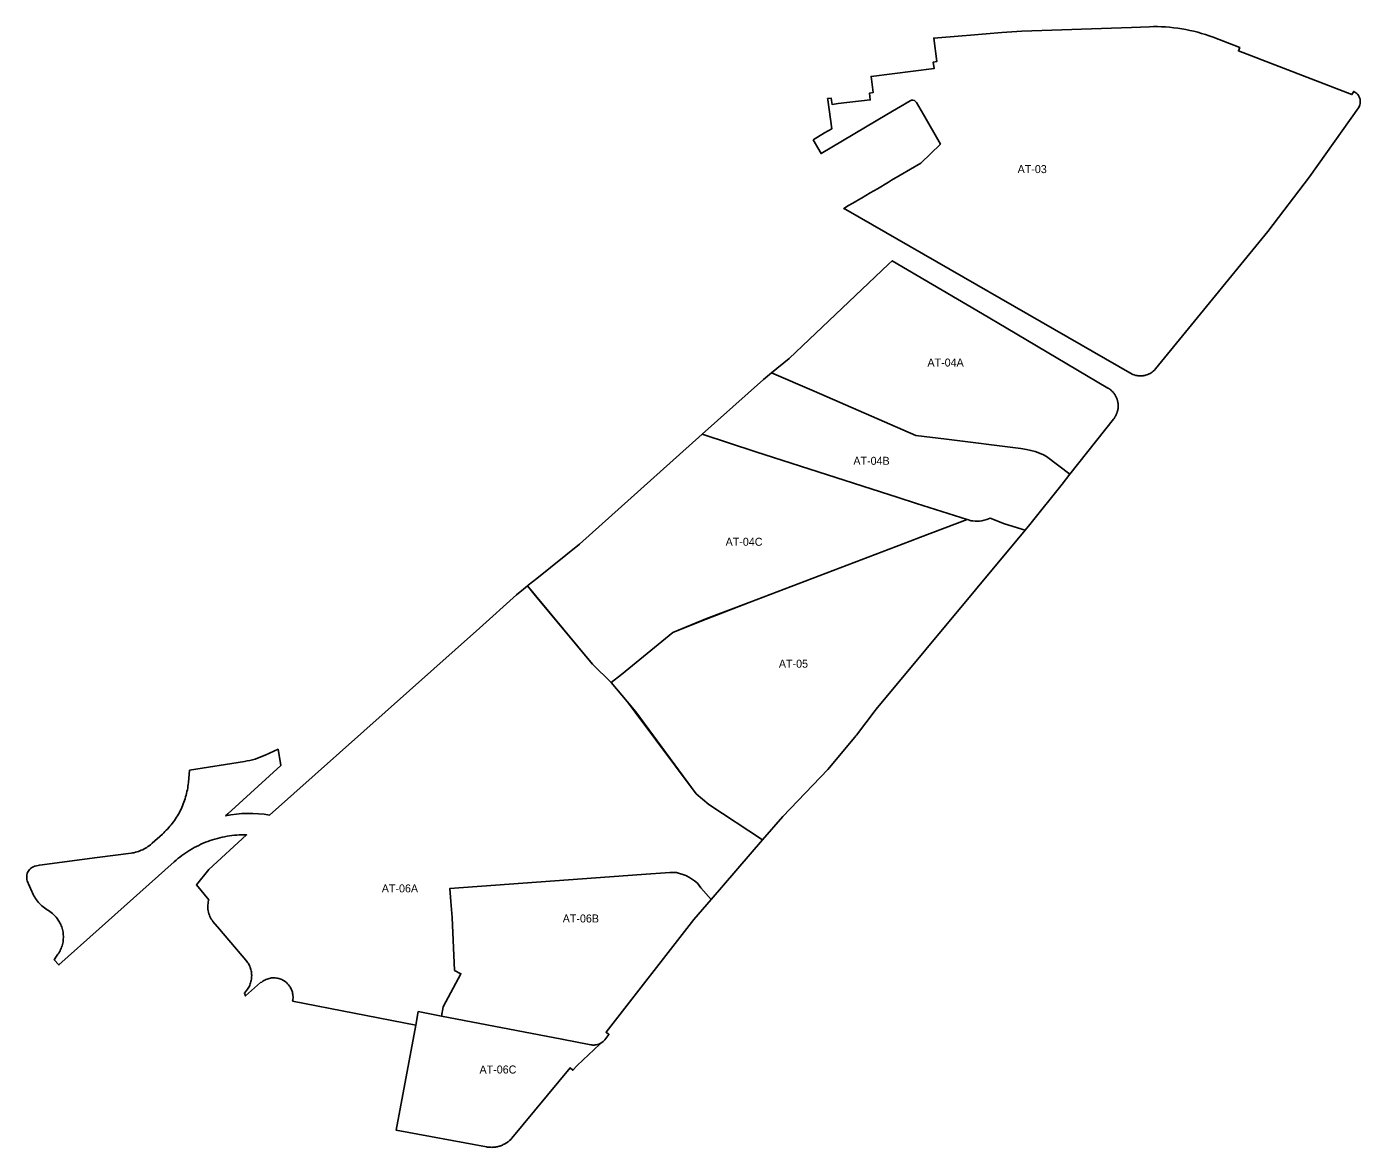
# Model space of a CAD drawing. Extents: x 428342 to 437063, y 4455780 to 4463043.
# Drawn here: x 431310 to 432143, y 4458647 to 4459347 of the extents above; entities that cross this region are included whole.
import ezdxf

# ---------------------------------------------------------------- set-up
doc = ezdxf.new("R2010")
doc.units = 0
doc.layers.add('AMB_SUNC-Residenciales', color=7, linetype='Continuous')
doc.layers.add('AMB_SUNC-Txt', color=7, linetype='Continuous')

msp = doc.modelspace()

# ---------------------------------------------------------------- linework, layer by layer
at = {"layer": 'AMB_SUNC-Residenciales'}
for points in [[(431800.91, 4459276.49), (431805.96, 4459267.89), (431847.1, 4459292.35), (431861.59, 4459300.94), (431862.46, 4459301.19), (431863.36, 4459301.2), (431864.24, 4459300.98), (431865.03, 4459300.53), (431865.67, 4459299.9), (431869.95, 4459292.35), (431880.49, 4459273.81), (431868.21, 4459261.94), (431855.36, 4459254.35), (431850, 4459251.19), (431847.99, 4459250), (431841.15, 4459245.96), (431836.62, 4459243.29), (431831.13, 4459240.05), (431828.81, 4459238.69), (431828.23, 4459238.36), (431827.15, 4459237.72), (431825.34, 4459236.66), (431823.11, 4459235.36), (431820.13, 4459233.62), (431821.47, 4459232.89), (432000.41, 4459130.05), (432000.83, 4459129.86), (432001.49, 4459129.6), (432002.64, 4459129.25), (432003.37, 4459129.09), (432004.11, 4459128.98), (432004.61, 4459128.93), (432005.11, 4459128.9), (432005.62, 4459128.89), (432006.13, 4459128.91), (432006.65, 4459128.94), (432007.16, 4459129), (432007.67, 4459129.08), (432008.17, 4459129.19), (432008.68, 4459129.31), (432009.42, 4459129.54), (432010.14, 4459129.81), (432010.84, 4459130.12), (432011.51, 4459130.48), (432012.15, 4459130.88), (432012.76, 4459131.31), (432013.52, 4459131.93), (432014.21, 4459132.59), (432014.83, 4459133.29), (432026.2, 4459147.18), (432085.16, 4459219.17), (432111.09, 4459253.37), (432141.7, 4459296.46), (432142.11, 4459297.15), (432142.35, 4459297.68), (432142.61, 4459298.44), (432142.79, 4459299.23), (432142.86, 4459299.83), (432142.88, 4459300.43), (432142.83, 4459301.23), (432142.68, 4459302), (432142.46, 4459302.74), (432142.15, 4459303.47), (432141.75, 4459304.16), (432141.28, 4459304.81), (432140.72, 4459305.4), (432140.11, 4459305.93), (432139.45, 4459306.37), (432138.75, 4459306.74), (432137.59, 4459304.78), (432066.72, 4459332.06), (432067.53, 4459334.16), (432050.87, 4459340.57), (432048.5, 4459341.45), (432046.11, 4459342.27), (432043.69, 4459343.03), (432041.25, 4459343.72), (432038.79, 4459344.36), (432036.31, 4459344.94), (432033.81, 4459345.45), (432031.3, 4459345.9), (432028.79, 4459346.28), (432026.26, 4459346.6), (432023.73, 4459346.86), (432021.19, 4459347.05), (432018.66, 4459347.18), (432016.12, 4459347.24), (432013.59, 4459347.24), (432011.07, 4459347.17), (432000, 4459346.74), (431931.28, 4459344.4), (431918.97, 4459343.68), (431899.26, 4459341.99), (431894.1, 4459341.56), (431876.38, 4459340.07), (431878.23, 4459325.45), (431876.03, 4459325.13), (431876.54, 4459321.05), (431837.23, 4459316.16), (431838.47, 4459306.06), (431836.21, 4459305.67), (431836.69, 4459301.49), (431816.67, 4459299.11), (431812.82, 4459298.65), (431812.48, 4459301.03), (431812.27, 4459302.51), (431810.05, 4459302.25), (431810.14, 4459301.58), (431812.6, 4459283.41), (431808.18, 4459280.83), (431800.91, 4459276.49)], [(431774.96, 4459130.86), (431801.66, 4459119.37), (431865.17, 4459091.68), (431884.21, 4459089.31), (431930.82, 4459083.49), (431934.21, 4459082.9), (431937.01, 4459082.28), (431939.76, 4459081.57), (431942.41, 4459080.64), (431944.83, 4459079.56), (431946.88, 4459078.53), (431961.4, 4459067.38), (431988.58, 4459101.84), (431988.79, 4459102.1), (431989, 4459102.38), (431989.2, 4459102.66), (431989.4, 4459102.94), (431989.59, 4459103.24), (431989.77, 4459103.53), (431989.94, 4459103.84), (431990.11, 4459104.15), (431990.27, 4459104.46), (431990.42, 4459104.79), (431990.56, 4459105.11), (431990.69, 4459105.44), (431990.82, 4459105.77), (431990.93, 4459106.11), (431991.04, 4459106.45), (431991.14, 4459106.8), (431991.22, 4459107.14), (431991.3, 4459107.49), (431991.37, 4459107.84), (431991.43, 4459108.19), (431991.48, 4459108.54), (431991.51, 4459108.9), (431991.54, 4459109.25), (431991.56, 4459109.6), (431991.57, 4459109.95), (431991.57, 4459110.31), (431991.56, 4459110.65), (431991.55, 4459111), (431991.52, 4459111.35), (431991.48, 4459111.69), (431991.44, 4459112.03), (431991.38, 4459112.37), (431991.32, 4459112.7), (431991.25, 4459113.04), (431991.17, 4459113.38), (431991.07, 4459113.71), (431990.97, 4459114.04), (431990.86, 4459114.38), (431990.75, 4459114.71), (431990.62, 4459115.03), (431990.48, 4459115.36), (431990.33, 4459115.68), (431990.18, 4459116), (431990.01, 4459116.32), (431989.84, 4459116.63), (431989.66, 4459116.93), (431989.47, 4459117.24), (431989.27, 4459117.53), (431989.06, 4459117.82), (431988.85, 4459118.11), (431988.62, 4459118.39), (431988.39, 4459118.66), (431988.16, 4459118.92), (431987.91, 4459119.18), (431987.66, 4459119.43), (431987.41, 4459119.68), (431987.15, 4459119.91), (431986.88, 4459120.14), (431986.61, 4459120.36), (431986.33, 4459120.57), (431986.05, 4459120.78), (431985.77, 4459120.97), (431985.48, 4459121.16), (431985.19, 4459121.33), (431921.63, 4459158.88), (431906.78, 4459167.65), (431850.39, 4459200.95), (431848.01, 4459198.69), (431785.93, 4459139.85), (431774.96, 4459130.86)], [(431731.67, 4459092.45), (431765.19, 4459081.52), (431854.21, 4459052.89), (431865.64, 4459049.22), (431897.3, 4459039.04), (431897.98, 4459038.84), (431899.01, 4459038.57), (431899.81, 4459038.41), (431900.81, 4459038.26), (431902.28, 4459038.12), (431903.79, 4459038.1), (431904.92, 4459038.16), (431906.44, 4459038.34), (431907.95, 4459038.64), (431909.61, 4459039.11), (431911.57, 4459039.89), (431920.64, 4459036.52), (431933.41, 4459032.4), (431936.45, 4459036.05), (431937.29, 4459037.06), (431956.59, 4459061.29), (431961.4, 4459067.38), (431946.88, 4459078.53), (431944.83, 4459079.56), (431942.41, 4459080.64), (431939.76, 4459081.57), (431937.01, 4459082.28), (431934.21, 4459082.9), (431930.82, 4459083.49), (431884.21, 4459089.31), (431865.17, 4459091.68), (431801.66, 4459119.37), (431774.96, 4459130.86), (431769.96, 4459126.75), (431731.67, 4459092.45)], [(431674.71, 4458937.29), (431681.21, 4458942.29), (431713.26, 4458968.59), (431734.04, 4458977.01), (431761, 4458987.27), (431861.63, 4459025.56), (431868.02, 4459028.04), (431897.3, 4459039.04), (431865.64, 4459049.22), (431854.21, 4459052.89), (431765.19, 4459081.52), (431731.67, 4459092.45), (431654.9, 4459023.67), (431628.29, 4459002.32), (431622.99, 4458998.07), (431622.43, 4458997.61), (431627.51, 4458991.53), (431663.21, 4458948.71), (431674.71, 4458937.29)], [(431735.8, 4458860.95), (431769.32, 4458838.82), (431782.03, 4458853.53), (431810.15, 4458882.82), (431826.96, 4458903.07), (431827.6, 4458903.84), (431827.98, 4458904.35), (431839.67, 4458919.81), (431840.31, 4458920.58), (431933.41, 4459032.4), (431920.64, 4459036.52), (431911.57, 4459039.89), (431909.61, 4459039.11), (431907.95, 4459038.64), (431906.44, 4459038.34), (431904.92, 4459038.16), (431903.79, 4459038.1), (431902.28, 4459038.12), (431900.81, 4459038.26), (431899.81, 4459038.41), (431899.01, 4459038.57), (431897.98, 4459038.84), (431897.3, 4459039.04), (431868.02, 4459028.04), (431861.63, 4459025.56), (431761, 4458987.27), (431734.14, 4458976.76), (431713.26, 4458968.59), (431681.21, 4458942.29), (431674.71, 4458937.29), (431684.79, 4458925.47), (431690.15, 4458918.83), (431727.9, 4458867.55), (431735.8, 4458860.95)], [(431730.83, 4458808.93), (431737.18, 4458801.59), (431769.32, 4458838.82), (431735.8, 4458860.95), (431727.9, 4458867.55), (431689.88, 4458918.64), (431684.79, 4458925.47), (431674.71, 4458937.29), (431663.21, 4458948.71), (431627.5, 4458991.52), (431622.43, 4458997.61), (431619.98, 4458995.66), (431615.57, 4458992.12), (431592.43, 4458971.26), (431461.3, 4458854.32)], [(431433.83, 4458853.9), (431435.19, 4458855.24), (431468.42, 4458885.44), (431466.71, 4458895.53), (431458.56, 4458891.8), (431457.01, 4458891.13), (431455.45, 4458890.5), (431453.86, 4458889.93), (431452.25, 4458889.42), (431450.62, 4458888.95), (431448.98, 4458888.55), (431447.34, 4458888.2), (431445.68, 4458887.9), (431411.39, 4458882.4), (431410.63, 4458874.68), (431410.5, 4458873.55), (431410.35, 4458872.43), (431410.18, 4458871.3), (431409.98, 4458870.18), (431409.75, 4458869.06), (431409.49, 4458867.94), (431409.21, 4458866.82), (431408.9, 4458865.71), (431408.57, 4458864.6), (431408.21, 4458863.49), (431407.82, 4458862.4), (431407.41, 4458861.31), (431406.97, 4458860.23), (431406.51, 4458859.16), (431406.02, 4458858.1), (431405.5, 4458857.06), (431404.97, 4458856.02), (431404.4, 4458855), (431403.82, 4458853.99), (431403.21, 4458853), (431402.58, 4458852.02), (431401.93, 4458851.06), (431401.25, 4458850.11), (431400.56, 4458849.18), (431399.85, 4458848.28), (431399.12, 4458847.39), (431398.37, 4458846.51), (431397.6, 4458845.66), (431396.81, 4458844.83), (431396.01, 4458844.02), (431395.2, 4458843.24), (431394.37, 4458842.47), (431387.99, 4458836.71), (431387.64, 4458836.4), (431386.91, 4458835.8), (431386.16, 4458835.21), (431385.38, 4458834.66), (431384.58, 4458834.13), (431383.76, 4458833.64), (431382.92, 4458833.17), (431382.07, 4458832.74), (431381.19, 4458832.34), (431380.3, 4458831.97), (431379.4, 4458831.64), (431378.49, 4458831.35), (431377.57, 4458831.09), (431376.64, 4458830.86), (431375.71, 4458830.68), (431374.78, 4458830.53), (431353.6, 4458827.9), (431317.51, 4458823.08), (431314.92, 4458822.45), (431314.57, 4458822.35), (431313.87, 4458822.1), (431313.19, 4458821.77), (431312.54, 4458821.37), (431311.94, 4458820.89), (431311.4, 4458820.35), (431310.92, 4458819.76), (431310.51, 4458819.14), (431310.18, 4458818.48), (431309.91, 4458817.79), (431309.72, 4458817.05), (431309.61, 4458816.3), (431309.58, 4458815.53), (431309.64, 4458814.77), (431309.77, 4458814.02), (431309.98, 4458813.31), (431312.77, 4458806.57), (431313.17, 4458805.66), (431313.6, 4458804.77), (431314.08, 4458803.88), (431314.59, 4458803.02), (431315.14, 4458802.17), (431315.72, 4458801.34), (431316.34, 4458800.53), (431316.99, 4458799.75), (431317.67, 4458799), (431318.38, 4458798.28), (431319.12, 4458797.59), (431319.88, 4458796.92), (431320.67, 4458796.3), (431321.48, 4458795.7), (431322.31, 4458795.15), (431323.15, 4458794.62), (431324.05, 4458794.06), (431324.92, 4458793.44), (431325.76, 4458792.77), (431326.57, 4458792.04), (431327.33, 4458791.27), (431328.06, 4458790.46), (431328.73, 4458789.61), (431329.36, 4458788.72), (431329.77, 4458788.07), (431330.16, 4458787.39), (431330.53, 4458786.69), (431330.87, 4458785.97), (431331.19, 4458785.22), (431331.47, 4458784.45), (431331.73, 4458783.66), (431331.95, 4458782.86), (431332.13, 4458782.03), (431332.28, 4458781.2), (431332.4, 4458780.35), (431332.48, 4458779.5), (431332.51, 4458778.64), (431332.51, 4458777.77), (431332.47, 4458776.91), (431332.39, 4458776.05), (431332.28, 4458775.19), (431332.12, 4458774.34), (431331.92, 4458773.49), (431331.69, 4458772.66), (431331.42, 4458771.85), (431331.12, 4458771.05), (431330.78, 4458770.27), (431330.41, 4458769.52), (431330.02, 4458768.78), (431329.59, 4458768.07), (431329.14, 4458767.39), (431328.66, 4458766.73), (431328.17, 4458766.1), (431326.79, 4458763.95), (431329.72, 4458760.67), (431354.88, 4458783.18), (431401.83, 4458825.14), (431402.96, 4458826.14), (431404.12, 4458827.12), (431405.3, 4458828.08), (431406.51, 4458829.01), (431407.75, 4458829.91), (431409.01, 4458830.79), (431410.3, 4458831.64), (431411.61, 4458832.46), (431412.94, 4458833.25), (431414.29, 4458834.01), (431415.66, 4458834.74), (431417.05, 4458835.44), (431418.46, 4458836.11), (431419.89, 4458836.74), (431421.33, 4458837.34), (431422.79, 4458837.9), (431424.26, 4458838.43), (431425.74, 4458838.92), (431427.23, 4458839.38), (431428.73, 4458839.8), (431430.24, 4458840.18), (431431.76, 4458840.53), (431433.28, 4458840.84), (431434.8, 4458841.11), (431436.33, 4458841.35), (431437.86, 4458841.55), (431439.39, 4458841.71), (431440.91, 4458841.83), (431442.44, 4458841.92), (431443.96, 4458841.98), (431445.47, 4458842), (431446.98, 4458841.98), (431423.44, 4458820.3), (431415.7, 4458810.66), (431423.37, 4458801.38), (431423.25, 4458800.95), (431423.05, 4458800.08), (431422.9, 4458799.18), (431422.8, 4458798.27), (431422.76, 4458797.35), (431422.78, 4458796.42), (431422.85, 4458795.48), (431422.99, 4458794.55), (431423.18, 4458793.63), (431423.42, 4458792.73), (431423.73, 4458791.84), (431424.08, 4458790.98), (431424.49, 4458790.15), (431424.94, 4458789.35), (431425.43, 4458788.59), (431425.96, 4458787.87), (431430.01, 4458783.1), (431446.58, 4458763.64), (431446.79, 4458763.38), (431447.2, 4458762.86), (431447.6, 4458762.3), (431447.97, 4458761.72), (431448.32, 4458761.12), (431448.65, 4458760.49), (431448.95, 4458759.84), (431449.22, 4458759.16), (431449.46, 4458758.47), (431449.67, 4458757.75), (431449.85, 4458757.03), (431449.99, 4458756.29), (431450.09, 4458755.54), (431450.15, 4458754.78), (431450.18, 4458754.01), (431450.16, 4458753.25), (431450.11, 4458752.48), (431450.02, 4458751.72), (431449.89, 4458750.97), (431449.72, 4458750.23), (431449.52, 4458749.5), (431449.28, 4458748.78), (431449.01, 4458748.09), (431448.71, 4458747.41), (431448.37, 4458746.76), (431448.01, 4458746.12), (431447.63, 4458745.52), (431447.22, 4458744.94), (431446.78, 4458744.39), (431446.34, 4458743.86), (431445.63, 4458743.13), (431446.4, 4458741.29), (431455.77, 4458749.73), (431456.49, 4458749.95), (431457.23, 4458750.5), (431457.83, 4458750.88), (431458.45, 4458751.23), (431459.1, 4458751.55), (431459.77, 4458751.83), (431460.47, 4458752.07), (431461.18, 4458752.26), (431461.91, 4458752.42), (431462.65, 4458752.52), (431463.39, 4458752.58), (431464.14, 4458752.6), (431464.88, 4458752.57), (431465.62, 4458752.49), (431466.34, 4458752.37), (431467.05, 4458752.21), (431467.74, 4458752), (431468.41, 4458751.76), (431469.06, 4458751.49), (431469.67, 4458751.18), (431470.45, 4458750.72), (431471.21, 4458750.2), (431471.93, 4458749.62), (431472.62, 4458748.96), (431473.26, 4458748.24), (431473.85, 4458747.46), (431474.13, 4458747.05), (431474.51, 4458746.42), (431474.85, 4458745.75), (431475.15, 4458745.07), (431475.4, 4458744.37), (431475.61, 4458743.66), (431475.78, 4458742.93), (431475.9, 4458742.2), (431475.98, 4458741.48), (431476.01, 4458740.75), (431476, 4458740.03), (431475.94, 4458739.33), (431475.85, 4458738.64), (431475.72, 4458737.96), (431552.69, 4458723.01), (431554.22, 4458731.52), (431568.86, 4458728.71), (431569.92, 4458734.43), (431580.94, 4458755.2), (431576.83, 4458757.26), (431575.43, 4458790.24), (431574.61, 4458800.43), (431574.07, 4458808.57), (431693.64, 4458817.15), (431711.44, 4458818.53), (431713.47, 4458818.47), (431715.51, 4458818.4), (431721.46, 4458816.61), (431723.66, 4458815.38), (431726.85, 4458813.36), (431728.76, 4458811.75), (431730.83, 4458808.93)], [(431730.83, 4458808.93), (431728.76, 4458811.75), (431726.85, 4458813.36), (431723.66, 4458815.38), (431721.46, 4458816.61), (431715.51, 4458818.4), (431713.47, 4458818.47), (431711.44, 4458818.53), (431693.64, 4458817.15), (431574.07, 4458808.57), (431574.61, 4458800.43), (431575.43, 4458790.24), (431576.83, 4458757.26), (431580.94, 4458755.2), (431569.92, 4458734.43), (431568.86, 4458728.71), (431644.06, 4458714.29), (431662.11, 4458710.78), (431662.7, 4458710.68), (431663.3, 4458710.63), (431664.22, 4458710.62), (431664.84, 4458710.67), (431665.46, 4458710.76), (431666.39, 4458710.98), (431667.43, 4458711.36), (431668, 4458711.64), (431668.95, 4458712.21), (431669.69, 4458712.78), (431670.32, 4458713.38), (431670.82, 4458713.94), (431673.41, 4458717.27), (431671.63, 4458718.65), (431726.34, 4458789.03), (431737.18, 4458801.59), (431730.83, 4458808.93)], [(431663.3, 4458710.63), (431662.7, 4458710.68), (431662.11, 4458710.78), (431644.06, 4458714.29), (431568.86, 4458728.71), (431554.22, 4458731.52), (431552.69, 4458723.01), (431540.43, 4458657.43), (431596.92, 4458646.94), (431597.45, 4458646.85), (431597.99, 4458646.78), (431598.54, 4458646.72), (431599.09, 4458646.68), (431599.65, 4458646.66), (431600.21, 4458646.65), (431600.77, 4458646.67), (431601.34, 4458646.7), (431601.9, 4458646.76), (431602.47, 4458646.83), (431603.03, 4458646.92), (431603.6, 4458647.03), (431604.16, 4458647.16), (431604.71, 4458647.31), (431605.27, 4458647.48), (431605.81, 4458647.67), (431606.35, 4458647.87), (431606.89, 4458648.1), (431607.41, 4458648.34), (431607.92, 4458648.6), (431608.43, 4458648.87), (431609.4, 4458649.47), (431610.33, 4458650.13), (431611.2, 4458650.84), (431612.01, 4458651.6), (431612.76, 4458652.39), (431649.16, 4458696.26), (431650.89, 4458694.83), (431653.45, 4458697.91), (431667.71, 4458711.07), (431667.43, 4458711.36), (431666.39, 4458710.98), (431665.46, 4458710.76), (431664.84, 4458710.67), (431664.22, 4458710.62), (431663.3, 4458710.63)]]:
    msp.add_lwpolyline(points, dxfattribs=at)
msp.add_arc((431448.65, 4458783.44), 72, 79.88362, 101.88101, dxfattribs=at)

# ---------------------------------------------------------------- texts
at = {"layer": 'AMB_SUNC-Txt'}
for s, p in [('AT-03', (431928.75, 4459255.69)), ('AT-04A', (431872.4, 4459134.77)), ('AT-04B', (431826.12, 4459073.33)), ('AT-04C', (431746.3, 4459022.72)), ('AT-05', (431779.57, 4458946.49)), ('AT-06A', (431531.46, 4458806.04)), ('AT-06B', (431644.52, 4458787.22)), ('AT-06C', (431592.53, 4458692.81))]:
    msp.add_text(s, height=5, dxfattribs=at).set_placement(p)

doc.saveas('drawing.dxf')
